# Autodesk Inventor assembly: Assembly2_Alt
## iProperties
Shininess: 64.0
Length Units: 11269
Angle Units: 11279
Time Units: 11290
Mass Units: 11283
Length Display Precision: 3
Angle Display Precision: 2
Compacted: True
Created: 2004-09
Part Number: Assembly2_Alt
Document SubType Name: Assembly
Designer: John Blackburn
Manufacturer: Standard
Standards Organization: Custom
Density: 0.0
Volumn: 0.0
Area: 0.0
PropertySet Name: Model Information
Control State: 0
Master: False
Checked Out: False
Author: John Blackburn
